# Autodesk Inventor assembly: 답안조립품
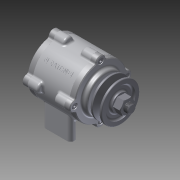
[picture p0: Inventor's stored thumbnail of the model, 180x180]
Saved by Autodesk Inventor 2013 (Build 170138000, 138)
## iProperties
Created: 2015-03
Part Number: 답안조립품
Document SubType Name: Assembly
Designer: Administrator
Author: Administrator
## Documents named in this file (11)
- C:\Users\Administrator\Desktop\450306V1003\답안조립품.iam
- C:\Users\Administrator\Desktop\450306V1003\본체.ipt
- C:\Users\Administrator\Desktop\450306V1003\베어링 6204.ipt
- C:\Users\Administrator\Desktop\450306V1003\축.ipt
- C:\Users\Administrator\Desktop\450306V1003\커버2.ipt
- C:\Users\Administrator\Desktop\450306V1003\커버.ipt
- C:\Users\Administrator\Desktop\450306V1003\오일실.ipt
- C:\Users\Administrator\Desktop\450306V1003\키(4 x 4 x 12).ipt
- C:\Users\Administrator\Desktop\450306V1003\V벨트풀리.ipt
- C:\Users\Administrator\Desktop\450306V1003\너트 M12x1.25.ipt
- C:\Users\Administrator\Desktop\450306V1003\M 4 x 12.ipt
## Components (14 placed, 6 different names)
1. KS B 2023 6204 - 20 x 47 x 14:1
2. KS B 2023 6204 - 20 x 47 x 14:2
3. KS B 2804 D D - 20 32 8:1
4. KS B 1311 (I) 4 x 4 x 12:1
5. 그루브 풀리1:1
6. KS B 1012 클래스 1 일반 - 미터 M12x1.25:1
7. KS B 1003 - 미터 M 4 x 12:1
8. KS B 1003 - 미터 M 4 x 12:2
9. KS B 1003 - 미터 M 4 x 12:3
10. KS B 1003 - 미터 M 4 x 12:4
11. KS B 1003 - 미터 M 4 x 12:5
12. KS B 1003 - 미터 M 4 x 12:6
13. KS B 1003 - 미터 M 4 x 12:7
14. KS B 1003 - 미터 M 4 x 12:8
